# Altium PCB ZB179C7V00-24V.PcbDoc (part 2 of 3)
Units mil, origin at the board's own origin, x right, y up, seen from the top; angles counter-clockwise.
Board outline 6000 x 4000 mil, 2 copper layers (Top Layer, Bottom Layer); 365 components, 297 nets, 1012 pads, 642 vias.
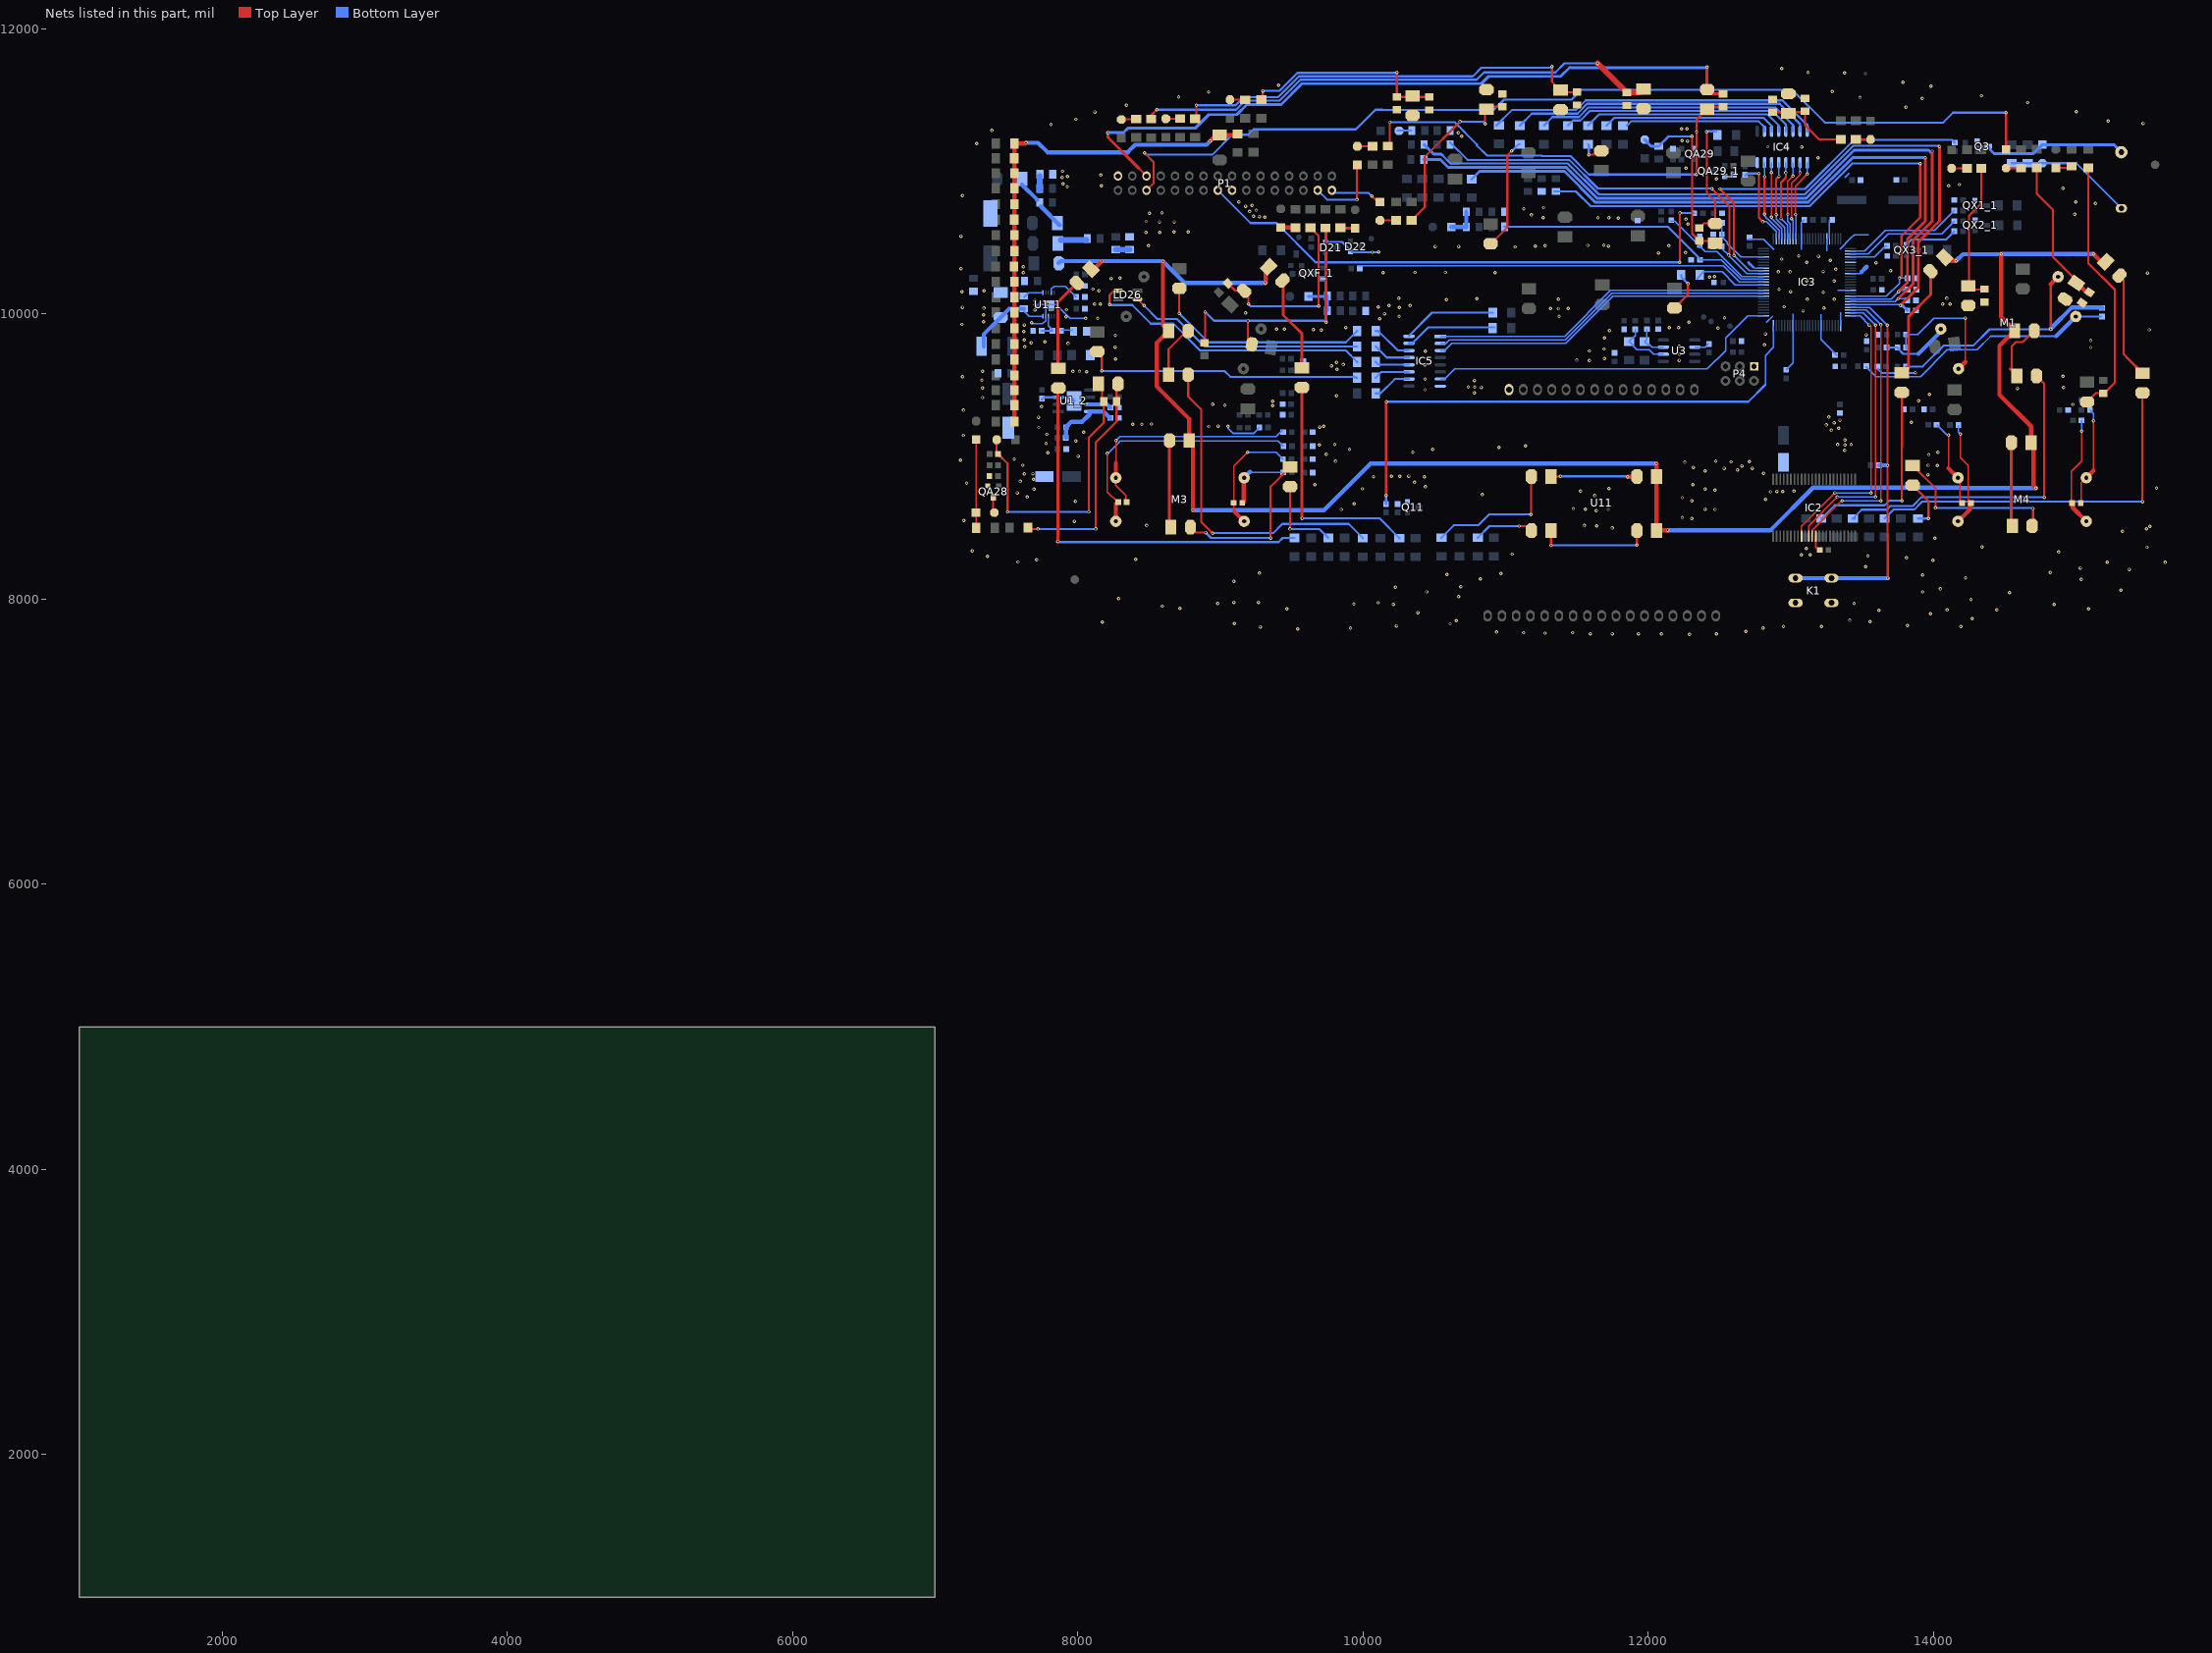
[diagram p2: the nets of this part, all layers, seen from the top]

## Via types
v1: diameter 23.62, hole 11.81, Top Layer to Bottom Layer, 642 vias

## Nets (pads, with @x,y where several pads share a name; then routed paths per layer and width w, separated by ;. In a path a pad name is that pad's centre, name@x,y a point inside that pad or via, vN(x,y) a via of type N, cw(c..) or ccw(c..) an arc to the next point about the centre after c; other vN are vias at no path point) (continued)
GND: C0.2 C1.2 C1_1.2 C2_1.1 C3_1.- C4.- C4_1.2 C5.1 C6.1 C7.1 C7_1.1 C8.1 C8_1.1 C9.1 C10.2 C11.2 C12.1 C13.1 C33.2 C35.2 C37.2 C38.1 C101.1 C102.1 C103.1 C301.1 C401.2 C501.2 CA18.2 CA22.2 CA23.2 CA101.2 CA251.2 CA261.2 CA601.1 CA1101.2 Cm1.1 Cm2.2 Cm3.2 Cm4.1 Cq1.1 Cq2.2 Cq3.2 Cq4.1 Cq21.1 Cq22.2 Cq23.2 Cq24.1 CS1.1 Cz1.1 Cz2.2 Cz3.2 Cz4.1 D3.1 D21.E D22.B DAL16.2 DAL18.2 DAL20.2 DAL21.2 DAL23.2 Ec01.2 Ec02.- IC2.13 IC3.1 IC3.8 IC3.18 IC3.61 IC3.70 IC3.71 IC3.91 IC4.8 IC5.8 K1.1 LC1_1.1 LC2_1.2 LDA03.2 LDA05.2 P1.9 P1.17 P4.2 Q3.E Q11.E QA28.E QA29.E QA29_1.E QX1_1.E QX2_1.E QX3_1.E QXF_1.E R4.1 R6_1.1 R36_1.1 R58.2 R302.2 R402.2 RA053_1.2 RA133.2 RA163.1 RA183.1 RA203.2 RA213.2 RA222.1 RA233.1 RA282.1 RA291_1.1 RA291_4.1 RA603.2 RA1103.1 RA1203.1 RT141.2 RX1_2.2 RX2_2.2 RX3_2.2 U1_1.9 U1_1.11 U1_2.0 U1_2.3 U3.2 U11.31 | length 4302.8
  Top Layer w15: 13175.97,8360.97 IC2.13@13175.97,8440.99
  Bottom Layer w9.8: v1(7678,9938) 7684.81,9931.19 7754,9931.19 7775.69,9952.88 U1_1.9@7775.69,9983.65 7775.69,10038.68 U1_1.11@7801,10064 ; 7701,10040 7725,10064 7793,10064 U1_1.11@7801,10064 ; v1(8056,9968) 7946,9968 7850,10064 U1_1.11@7801,10064 ; U3.2@12327,9767 12327.4,9767.4 12399.4,9767.4 C33.2@12425,9793 ; CS1.1@12697,10524 12810.15,10524 12882.07,10452.07 ; C5.1@12968,9608 13016.57,9656.57 IC3.18@13016.57,9917.85 13016.64,9917.91 13016.64,10000.36 ; 13075.63,10449.37 IC3.61@13075.63,10528.09 13075.63,10639.63 C102.1@13096,10660 ; 13213.42,9997.58 IC3.8@13213.42,9917.85 13213.42,9821.03 C9.1@13326.45,9708 ; 13252.79,10439.21 IC3.70@13252.79,10528.09 ; IC3.71@13272.48,10528.09 C103.1@13272.48,10658.31 ; 13330.09,10163.91 IC3.91@13420.12,10163.91 ; IC3.1@13351.22,9917.85 13351.22,10010.78 ; 13423.66,10532.66 13445,10554 13548,10554
  Bottom Layer w12: v1(9054,9212) 9054,9199 9092,9161 9233,9161 Cz3.2@9275,9203 ; 12832,9944 12833.35,9944 12871,9981 ; 13346,10455 13423.66,10532.66 ; 13382,10958 13408,10984
  Bottom Layer w15: C1_1.2@7749,9401 7763,9415 U1_2.3@7864,9415 ; D21.E@9737.62,10504 9854,10504 9925,10433 v1(10111,10433) ; 13612,9611 13637,9586 13868,9586 v1@13872,9590 ; QX3_1.E@13810.62,10486 13846.62,10522 14090,10522 RX2_2.2@14148,10580
  Bottom Layer w20: U1_2.3@7864,9415 7949,9415 U1_2.0@7974,9390
  other v1: 12291,7753 12095,7755 12479,7755 11595,7757 11748,7757 11932,7757 11277,7761 11126,7764 11471,7764 10937,7768 12685,7772 9543,7790 9913,7796 12805,7797 9280,7805 12949,7808 13216,7808 14192,7808 10236,7812 13817,7815 10612,7826 9099,7827 8172,7838 13556,7842 10655,7849 13414,7851 14273,7863 13981,7897 10386,7905 13618,7920 14097,7923 14446,7925 9468,7931 15088,7932 8717,7934 8593,7950 10213,7962 14847,7963 9937,7966 8983,7969 13445,7969 10108,7974 9096,7977 9267,7977 14264,7997 8288,8004 10671,8018 14535,8045 10447,8050 13925,8050 15316,8061 14050,8071 10229,8083 10687,8086 9094,8124 15038,8137 10823,8142 14226,8148 13926,8168 10589,8172 10969,8179 9274,8181 14821,8186 15373,8208 15031,8218 13526,8228 15626,8257 15220,8258 7582,8260 13997,8272 7713,8275 8407,8278 13812,8288 7368,8299 13541,8302 13074,8309 13137,8310 11047,8315 14879,8329 7262,8338 13109,8355 15497,8363 14340,8364 14011,8426 15327,8475 15494,8492 11748,8498 15519,8510 11640,8512 8484,8515 11552,8515 7976,8545 7201,8551 12306,8564 12240,8570 11637,8619 9848,8628 11720,8628 12470,8628 11560,8630 12399,8631 11476,8632 9938,8667 7985,8685 12306,8689 12824,8699 12240,8711 7647,8715 11627,8725 10838,8732 7576,8745 12859,8752 12944,8754 12902,8755 13024,8756 11527,8758 12468,8764 7693,8772 12399,8772 9997,8773 11726,8775 15565,8778 10438,8787 9664,8803 12314,8803 7221,8813 10363,8818 7597,8825 7691,8839 10430,8857 10075,8858 10200,8860 10259,8860 10322,8862 13963,8872 7627,8878 7686,8879 12811,8881 12400,8898 12626,8906 12533,8917 12730,8917 12317,8924 12659,8934 14029,8937 7616,8938 13964,8938 12257,8959 12583,8962 12709,8963 9809,8966 12474,8968 7179,8975 7555,8981 8003,9003 13968,9011 9744,9015 7791,9026 10350,9029 14033,9030 13379,9043 9906,9050 10491,9050 10955,9064 11140,9074 13380,9080 9695,9081 13330,9083 13424,9084 9803,9085 7779,9092 7986,9109 13380,9116 7198,9148 7784,9155 8042,9171 13286,9183 13337,9197 7727,9203 9697,9206 8921,9210 9726,9211 8986,9213 13249,9221 8387,9226 8450,9226 8517,9227 13304,9235 13845,9239 13345,9254 7724,9275 13267,9276 7200,9324 7746,9348 9368,9357 9032,9360 14979,9365 8946,9367 9368,9388 13896,9391 7332,9413 9816,9426 13973,9435 10781,9445 10436,9468 14588,9478 7332,9480 14914,9483 10829,9485 10739,9487 10784,9487 10782,9533 7328,9536 10436,9543 7193,9560 14910,9562 13875,9588 8063,9594 7967,9596 8013,9596 7332,9598 9819,9611 9779,9635 10435,9642 9862,9644 9816,9660 11589,9673 12219,9674 11500,9675 8266,9683 11693,9686 12220,9717 10437,9738 11587,9740 11691,9754 15104,9764 8263,9767 7630,9768 12218,9772 12816,9782 7933,9792 7675,9796 7770,9804 15104,9813 7626,9817 11694,9832 8264,9849 13528,9853 12822,9860 7623,9876 11730,9883 9707,9887 15514,9888 9652,9889 9395,9893 9450,9893 12491,9901 12148,9904 12213,9904 9880,9905 7626,9922 7188,9926 12286,9941 7340,9944 10117,9965 8140,9969 12536,9972 7919,9980 11376,9982 10254,9983 7340,9993 10151,10001 9177,10007 13087,10022 7700,10027 7921,10029 11372,10036 11316,10038 11440,10038 7342,10040 13232,10042 10256,10045 7193,10046 10107,10049 12955,10050 10331,10057 10184,10059 7700,10062 8119,10068 8159,10068 14065,10068 14118,10068 7793,10071 7734,10074 7701,10094 10587,10100 13116,10102 13306,10102 11372,10103 10800,10107 14095,10109 10251,10111 13228,10152 7188,10154 12999,10156 7344,10162 8150,10162 12918,10172 8107,10174 13112,10230 13304,10230 8234,10249 8297,10251 12431,10259 12465,10262 15502,10287 7620,10289 10142,10290 10927,10290 10366,10291 10578,10291 12912,10295 12997,10295 13228,10297 13700,10302 13315,10312 7183,10316 7620,10330 13597,10359 13112,10361 13277,10376 12938,10384 13194,10404 13056,10407 12074,10428 12262,10429 10067,10432 11067,10470 10508,10473 10671,10473 11209,10475 11722,10476 8496,10477 12146,10477 11279,10478 11576,10480 11689,10482 7182,10545 8478,10571 8576,10571 8776,10574 8676,10575 12280,10630 8574,10645 8677,10645 8481,10649 12265,10663 11790,10671 11264,10674 11648,10674 11724,10674 9313,10678 9273,10683 9232,10685 11181,10694 14991,10698 8502,10705 8591,10710 9205,10718 9252,10725 11128,10737 11269,10745 9179,10755 9224,10760 15138,10775 14999,10784 9131,10785 7193,10829 14908,10882 7927,10892 14108,10897 8166,10899 14183,10907 7898,10913 12480,10947 7892,10956 7928,10963 8162,10973 7895,11000 12266,11022 13191,11094 13077,11171 12839,11172 12961,11174 7291,11194 12277,11213 12239,11215 10692,11247 10670,11271 7399,11286 12235,11297 12272,11297 7813,11328 15472,11337 15226,11353 7987,11365 8120,11416 15003,11418 13809,11449 8343,11462 14662,11482 13923,11511 13486,11517 8708,11522 14338,11530 8918,11556 13291,11558 13984,11597 9408,11605 13788,11624 13524,11685 13378,11690 13121,11693 12938,11722
HEADLIGHT+: DA15.1 P1.15 | length 547.7
  Top Layer w15: v1(9958,10801) 9958,11042 DA15.1@9961,11045
  Bottom Layer w15: P1.15@9682.79,10866.69 9748.48,10801 v1(9958,10801)
HEADLIGHT-: DAL15.2 P1.19 RA153.2 | length 5086
  Top Layer w15: 8430.48,11019 P1.19@8482.79,10966.69
  Top Layer w20: v1(8212,11271) 8212,11237.48 8430.48,11019 ; DAL15.2@12413,11574.82 v1(12413,11731) ; DAL15.2@12413.63,11574.19 12444.82,11543 RA153.2@12525,11543
  Bottom Layer w20: v1(8212,11271) 8323,11271 8356,11304 8827,11304 8920.5,11397.5 9116.5,11397.5 9187.5,11468.5 9426.98,11468.5 9572.99,11614.51 10830.51,11614.51 10882,11666 11387,11666 11451,11730 ; 11458.28,11726 11636,11726 ; 11633.03,11725.69 12407.69,11725.69 v1(12413,11731)
KEY: IC3.97 K1.2 R6.1 | length 2798.1
  Top Layer w9.8: v1@13680,8140 v1(13680,8146)
  Top Layer w15: v1(13678,9920) 13679,9919 v1(13679,8937) 13679,8409 ; v1(13680,8146) 13680,8408
  Bottom Layer w9.8: IC3.97@13420.12,10045.8 13552.2,10045.8 v1(13678,9920) ; v1@13678,8938 v1(13679,8937) ; v1@13679.39,8146.61 v1(13680,8146)
  Bottom Layer w15: v1(13678,9920) v1@13678,9923
  Bottom Layer w30: K1.2@13034.02,8146.61 K1.2@13285.98,8146.61 v1@13679.39,8146.61 ; R6.1@13620,8938 v1@13678,8938
LIGHT: P1.8 RA1102.2 | length 3896.9
  Top Layer w15: v1(12222,10362) 12222,10707 v1(12223,10708)
  Bottom Layer w15: P1.8@8982.79,10866.69 9212.48,10637 9394,10637 9669,10362 v1(12222,10362) ; v1(12223,10708) 12321,10708 RA1102.2@12324,10705
"LOW SHIFT+": DA03.1 P1.3 | length 6930.7
  Top Layer w15: v1(8468,11129) 8532,11065 8532,10915.91 P1.3@8482.79,10866.69 ; DA03.1@14510,11152.5 v1(14510,11412)
  Bottom Layer w15: v1(8468,11129) 8480.81,11116.19 8943.84,11116.19 9079.65,11252 9084.7,11252 9088.7,11256 9195.18,11256 9233.68,11294.5 9950.47,11294.5 10088.47,11432.5 10137.33,11432.5 10139.83,11430 10917.44,11430 10990.44,11503 11464.07,11503 11532.07,11571 13009.82,11571 13239.32,11341.5 14069.15,11341.5 14138.84,11411.19 14509.19,11411.19 v1(14510,11412)
LOWLIGHT+: DA26.1 P1.16 | length 371.1
  Top Layer w15: v1(10062,10826) 10103,10785 DA26.1@10120,10785
  Bottom Layer w15: P1.16@9782.79,10866.69 9800.48,10849 10039,10849 v1(10062,10826)
"MIEXHAUST BRAKE+": CA22.1 IC3.41 RA223.2 | length 2890.5
  Top Layer w15: v1(12447,10877) 12571,10753 12571,10419 v1(12564,10412)
  Bottom Layer w9.8: CA22.1@12518,10491 12518,10458 v1(12564,10412) 12564,10409.93 12691.91,10282.02 IC3.41@12809.88,10282.02
  Bottom Layer w15: RA223.2@10611,11203 10734,11080 11447.35,11080 11648.35,10879 12447,10879 v1(12447,10877)
MIFUEL: C501.1 IC3.94 R505.1 | length 4867.8
  Top Layer w20: v1(13756,10156) 13818,10218 13818,10525 13944,10651 v1(13944,11094)
  Bottom Layer w9.8: IC3.94@13420.12,10104.86 13420.27,10104.7 13704.7,10104.7 v1(13756,10156)
  Bottom Layer w20: R505.1@10764,10945 10818,10999 11413.8,10999 11630.8,10782 13121.2,10782 13135.21,10796.01 13436.2,11097 13941,11097 v1(13944,11094) ; v1(13756,10156) 13770,10170 C501.1@13821,10170
MILIGHT: CA1101.1 IC3.47 RA1104.2 | length 455.7
  Bottom Layer w9.8: CA1101.1@12516,10565 12517,10564 12517,10541.8 12556.47,10502.33 12556.47,10493.47 12650.14,10399.79 12809.54,10399.79 IC3.47@12809.88,10400.13 ; CA1101.1@12518,10563 RA1104.2@12518,10638
MISAFEBELT: CA101.1 IC3.39 RA1204.2 | length 1976.7
  Bottom Layer w9.8: CA101.1@12363,10379 12513.71,10379 12650.05,10242.65 IC3.39@12809.88,10242.65
  Bottom Layer w15: RA1204.2@10990,10610 12140,10610 12363,10387 CA101.1@12363,10379
MISENSE1: CA251.1 IC3.96 RA251.1 | length 5542.6
  Top Layer w20: v1(13769,10059) 13894,10184 13894,10503 14043,10652 v1(14043,11173)
  Bottom Layer w9.8: IC3.96@13420.12,10065.49 13762.51,10065.49 v1(13769,10059)
  Bottom Layer w15: 10558,11112 10614.5,11055.5 11437.2,11055.5 11654.2,10838.5 13097.8,10838.5 13437.3,11178 14038,11178 v1(14043,11173)
  Bottom Layer w20: RA251.1@10430,11187 10497,11120 10550,11120 10558,11112 ; v1(13769,10059) 13783,10059 CA251.1@13818,10024
MISENSE2: CA261.1 IC3.95 RA261.1 | length 5374.2
  Top Layer w20: v1(13752,10105) 13859,10212 13859,10517 13992,10650 v1(13992,11141)
  Bottom Layer w9.8: IC3.95@13420.12,10085.17 13732.17,10085.17 v1(13752,10105) 13810,10105 CA261.1@13820,10095
  Bottom Layer w20: RA261.1@10427,11083 10543,11083 10597.5,11028.5 11426.02,11028.5 11643.02,10811.5 13108.98,10811.5 13444.98,11147.5 13968.12,11147.5 13983.31,11132.31 v1(13992,11141)
MISTATUS: C301.2 IC3.40 R303.1 | length 815
  Bottom Layer w9.8: R303.1@12155,10649 12187,10649 12400,10436 12484,10436 12657.66,10262.34 IC3.40@12809.88,10262.34
MIVOLTAGE: C401.1 IC3.93 R403.1 | length 4072.2
  Top Layer w15: v1(13762,10250) 13777,10265 13777,10546 13908,10677 v1(13908,11054)
  Bottom Layer w9.8: IC3.93@13420.12,10124.54 13671.54,10124.54 13762,10215 v1(13762,10250) 13821,10250 C401.1@13822,10249
  Bottom Layer w15: R403.1@11342,10859 R403.1@11354,10859 11493,10859 11597,10755 13132.38,10755 13431.38,11054 v1(13908,11054)
MOABS: IC3.52 RA291_3.1 | length 624.7
  Top Layer w15: v1(12777,10984) 12777,10674 v1(12805,10646)
  Bottom Layer w9.8: v1(12805,10646) 12831,10646 12898.1,10578.9 12898.1,10528.45 IC3.52@12898.46,10528.08
  Bottom Layer w15: RA291_3.1@12680,10969 12695,10984 v1(12777,10984)
MOAF2301: IC3.38 R3_1.2 | length 2895.4
  Bottom Layer w9.8: R3_1.2@9961.21,10335.79 12527.21,10335.79 12640.03,10222.97 IC3.38@12809.88,10222.97
"MOAIR PRESSURE": IC3.56 IC4.4 | length 565.7
  Top Layer w15: v1(12932,10669) 12932,10921 12966,10955 v1(12966,10990)
  Bottom Layer w9.8: v1(12932,10669) 12977.2,10623.8 IC3.56@12977.2,10528.08 ; v1(12966,10990) IC4.4@12966,11061
MOAIR_FAULT: IC3.33 IC5.3 | length 2424.9
  Bottom Layer w9.8: IC5.3@10543,9743 10573,9743 10624,9794 11421.59,9794 11752.13,10124.54 IC3.33@12809.88,10124.54
MOAIR_HOT: IC3.77 RX1_1.1 | length 846.1
  Bottom Layer w9.8: IC3.77@13420.12,10439.5 13519.5,10439.5 13664,10584 14007,10584 RX1_1.1@14148,10725
MOAIRFLITER: IC3.78 RX2_1.1 | length 824.2
  Bottom Layer w9.8: IC3.78@13420.12,10419.82 13543.82,10419.82 13685,10561 14058,10561 14058.5,10560.5 14147,10649 RX2_1.1@14147,10651
MOBUZZER: IC3.42 RA12.2 | length 2558.1
  Top Layer w15: v1(12504,10876) 12602,10778 v1(12602,10409)
  Bottom Layer w9.8: v1(12602,10409) 12709.29,10301.71 IC3.42@12809.88,10301.71
  Bottom Layer w15: v1(12504,10876) 13100.65,10876 13445.65,11221 14131,11221 RA12.2@14151,11201
MODRIVERALARM: IC3.59 IC4.1 | length 568.6
  Top Layer w9.8: v1(13034,10697) 13034,10896.41 13117,10979.41 v1(13117,10980)
  Bottom Layer w9.8: v1(13034,10697) 13036.26,10694.74 IC3.59@13036.26,10528.09 ; IC4.1@13116,11061 13116,10981 v1(13117,10980)
MOENGINE_FAULT: IC3.57 IC4.3 | length 555.8
  Top Layer w9.8: v1(12980,10698) 12980,10930 v1(13016,10966)
  Bottom Layer w9.8: v1(12980,10698) 12978.79,10696.79 12978.79,10649.51 12996.89,10631.41 IC3.57@12996.89,10528.09 ; v1(13016,10966) IC4.3@13016,11061
MOFUEL: IC3.34 IC5.2 | length 2412.4
  Bottom Layer w9.8: IC5.2@10543,9793 10581,9793 10607,9819 11419.29,9819 11744.52,10144.23 IC3.34@12809.88,10144.23
MOHOT: IC3.58 IC4.2 | length 563
  Top Layer w9.8: v1(13005,10667) 13006.21,10668.21 13006.21,10915.21 13066,10975 v1(13066,10990)
  Bottom Layer w9.8: v1(13005,10667) 13016.57,10655.43 IC3.58@13016.57,10528.09 ; v1(13066,10990) IC4.2@13066,11061
MOLCD: IC3.25 RT131.1 | length 3864.2
  Top Layer w15: v1(10163,8726) 10163,9383 10164,9384 v1(10165,9384)
  Bottom Layer w9.8: 12822,9502 12822,9709 12878.78,9765.78 IC3.25@12878.78,9917.85
  Bottom Layer w15: RT131.1@10163,8666.5 v1(10163,8726) ; v1(10165,9384) 12704,9384 12822,9502
MOLCDCS: IC2.9 IC3.100 | length 1998.9
  Top Layer w9.8: IC2.9@13075.97,8440.99 13075.97,8508.97 13313,8746 v1@13313,8749 ; v1(13551,9922) 13562,9911 13562,8770 13562,8745 v1(13563,8744)
  Bottom Layer w9.8: v1@13313,8749 13318,8744 v1(13563,8744) ; IC3.100@13420.12,9986.75 13486.25,9986.75 v1(13551,9922)
  other v1: 13310,8745
MOLCDDA: IC2.12 IC3.98 | length 2102
  Top Layer w12: IC2.12@13150.97,8440.99 13150.97,8486 13153.06,8486 13355.06,8688 v1(13360,8688) ; v1(13632,8688) 13632,9922 v1(13633,9923)
  Bottom Layer w9.8: IC3.98@13420.12,10026.12 13529.88,10026.12 v1(13633,9923)
  Bottom Layer w12: v1(13360,8688) 13360.31,8687.69 13631.69,8687.69 v1(13632,8688) ; v1(13633,9923) v1@13633,9924
MOLCDWR: IC2.11 IC3.99 | length 2041
  Top Layer w9.8: IC2.11@13125.97,8440.99 13125.97,8513.97 v1(13327,8715) ; v1(13595,8715) v1(13595,9920)
  Bottom Layer w9.8: v1(13327,8715) v1(13595,8715) ; IC3.99@13420.12,10006.43 13508.57,10006.43 v1(13595,9920)
MOOBD: IC3.53 IC4.7 | length 575.4
  Top Layer w15: v1(12816,10698) v1(12816,10962)
  Bottom Layer w9.8: v1(12816,10698) 12816,10688 12838.7,10665.3 12838.99,10665.3 12918.15,10586.15 IC3.53@12918.15,10528.08 ; v1(12816,10962) IC4.7@12816,11061
MOOIL_WATER: IC3.54 IC4.6 | length 563.5
  Top Layer w9.8: v1(12865,10679) v1(12865,10991)
  Bottom Layer w9.8: v1(12865,10679) 12865,10671.64 12937.83,10598.8 IC3.54@12937.83,10528.08 ; v1(12865,10991) 12866,10992 IC4.6@12866,11061
MOOILPRESS: IC3.26 IC5.7 | length 2503.4
  Bottom Layer w9.8: IC5.7@10543,9543 10573,9543 10643,9613 12415,9613 12545,9743 12545,9833 12698.75,9986.75 IC3.26@12809.88,9986.75
MOSAFEBELT: IC3.35 IC5.1 | length 2399.8
  Bottom Layer w9.8: IC5.1@10543,9843 11416,9843 11736.91,10163.91 IC3.35@12809.88,10163.91
MOSPEED1: IC3.81
MOSVS: IC3.43 | length 110.6
  Bottom Layer w9.8: 12742.61,10321.39 IC3.43@12809.88,10321.39
  Bottom Layer w20: 12705.39,10358.61 12736,10328
MOTEMP: IC3.37 RDX1.2 | length 528.6
  Bottom Layer w9.8: RDX1.2@12340,10245 12390,10295 12519,10295 12610.72,10203.28 IC3.37@12809.88,10203.28
MOTMPS: IC3.79 RX3_1.1 | length 287.3
  Bottom Layer w9.8: IC3.79@13420.12,10400.13 13588.13,10400.13 13664,10476 RX3_1.1@13676,10476
MOTRANSFALT: IC3.85 | length 128.4
  Bottom Layer w9.8: IC3.85@13420.12,10282.02 13499.02,10282.02
  Bottom Layer w30: 13497.02,10295.02 13532,10330
MOUREA: IC3.55 IC4.5 | length 566.7
  Top Layer w15: v1(12898,10696) 12898,10945 v1(12918,10965)
  Bottom Layer w9.8: v1(12898,10696) 12898,10665.93 12957.16,10606.78 12957.16,10528.45 IC3.55@12957.52,10528.08 ; IC4.5@12916,11061 12918,11059 v1(12918,10965)
NetB1_1: B1.1 D10.2 RA9.1 RA10.1 | length 900.6
  Bottom Layer w15: RA10.1@14549,11056.5 RA9.1@14662,11056.5 15002.15,11056.5 B1.1@15318.58,10740.07
NetB1_2: B1.2 D10.1 Q3.C | length 1010.8
  Bottom Layer w20: Q3.C@14376.62,11174 14426.62,11124 14702,11124 D10.1@14765,11187 15265.35,11187 B1.2@15318.58,11133.77
NetC2_1: C2.1 U1_1.1 | length 150.3
  Bottom Layer w10: C2.1@7621,10112 7658,10149 U1_1.1@7756,10149
NetC2_1_2: C2_1.2 U1_2.7 | length 154.5
  Bottom Layer w30: U1_2.7@8084,9365 8206,9365 C2_1.2@8229,9342
NetC2_2: C2.2 D3.2 L1_1.2 U1_1.10 | length 589.1
  Bottom Layer w10: C2.2@7621,10022 7659.35,9983.65 U1_1.10@7756,9983.65
  Bottom Layer w30: L1_1.2@7341.75,9773 7341.75,9856.75 D3.2@7460,9975 7521,10036 C2.2@7622,10036
NetC3_2_2: C3_2.2 R57.1 R58.1 U1_2.8 | length 460.9
  Bottom Layer w30: R57.1@7917,9133 7917,9204 C3_2.2@7918,9205 7955,9242 8031,9242 8083,9294 U1_2.8@8083,9315 8181.35,9315 8226.35,9270 R58.1@8230,9270
NetC6_2: C6.2 R3_2.2 U1_1.8 | length 184.5
  Bottom Layer w10: U1_1.8@7795.37,9983.65 7795.37,9915.63 R3_2.2@7824,9887
  Bottom Layer w15: C6.2@7748,9882 R3_2.2@7824,9882
NetC7_1_2: C7_1.2 U1_1.4 | length 241.3
  Bottom Layer w9.8: U1_1.4@7815.06,10149 7815.06,10175.06 7834,10194 7915,10194 C7_1.2@7991,10118
NetC8_1_2: C8_1.2 R3_2.1 | length 81.4
  Bottom Layer w10: R3_2.1@7883,9888 7963,9888 C8_1.2@7964,9889
NetCA18_1: CA18.1 DAL18.1 RA182.2 RA183.2 | length 620.7
  Top Layer w15: RA183.2@12873,11415 13095,11415 CA18.1@13101,11421 13101,11321 13198,11224 RA182.2@13351,11224
NetCA23_1: CA23.1 DAL23.1 RA232.2 RA233.2 | length 1461.8
  Top Layer w15: RA232.2@9288,11502 9298,11512 v1(9298,11564) ; v1(10238,11695) CA23.1@10238,11522 10465,11522 RA233.2@10466,11521
  Bottom Layer w15: v1(9298,11564) 9415,11564 9541.51,11690.51 10233.51,11690.51 v1(10238,11695)
NetD1_1: D1.1 L1.1 | length 177
  Bottom Layer w40: D1.1@7883,10518 L1.1@8060,10518
NetD2_1: D2.1 D3_1.1 L2.1 | length 336.6
  Bottom Layer w30: D3_1.1@7610,10906 L2.1@7716,10800 ; L2.1@7742,10754 D2.1@7874,10622
NetD4_2: D4.2 DL2.1 DL3.1 DL6.1 DL8.1 DL10.1 DL11.1 LD2.1 LD3.1 LD13.1 LD14.1 | length 13299.3
  Top Layer w30: DL2.1@8092.98,10314.46 8114.46,10314.46 v1(8170,10370) ; v1(8598,10368) 8598,9918.76 LD2.1@8637.39,9879.37 8554,9795.98 8554,9492 8781,9265 LD13.1@8781,9112 8808,9085 v1(8808,8623) ; v1(9315,10218) 9318,10221 9318,10308.44 DL3.1@9339.54,10329.98 ; v1(12057,8950) 12059.61,8947.39 DL6.1@12059.61,8859.63 DL8.1@12059.61,8479.63 ; DL8.1@12062.98,8483 v1(12137,8483) v1@12133.63,8479.63 ; DL10.1@14079,10397 14105,10371 v1(14159,10371) ; v1(14475,10419) 14476,10420 14476,9976.76 LD3.1@14570.39,9882.37 14464,9775.98 14464,9432 14685,9211 LD14.1@14685,9097 14702.04,9079.96 14702.04,8794.96 v1(14720,8777) ; v1(15123,10419) 15176,10366 DL11.1@15209,10366
  Bottom Layer w30: D4.2@7867,10356 7881,10370 v1(8170,10370) 8596,10370 v1(8598,10368) 8748,10218 v1(9315,10218) ; v1(8808,8623) 9727,8623 10054,8950 v1(12057,8950) ; v1(12137,8483) 12859,8483 13157.31,8781.31 14189.69,8781.31 14194,8777 v1(14720,8777) ; v1(14159,10371) 14206.69,10418.69 14474.69,10418.69 v1(14475,10419) v1(15123,10419)
NetD7_1: D7.1 R18.1 R19.1 R20.1 R21.1 R22.1 R23.1 R24.1 R25.1 R26.1 R27.1 R28.1 R29.1 R30.1 R31.1 R32.1 R33.1 R34.1 R35.1 R36.1 R37_1.1 | length 3598.8
  Top Layer w30: R18.1@7556,9245 R19.1@7556,9360 R20.1@7556,9464 R21.1@7556,9568 R22.1@7556,9680 R23.1@7556,9789 R24.1@7556,9899 R25.1@7556,10010 R27.1@7556,10225 R29.1@7556,10441 R30.1@7556,10552 R32.1@7556,10770 R33.1@7556,10881 R34.1@7556,10986 R36.1@7556,11195 7633,11195 v1(7638,11200) ; v1(8929,11211) 8972,11254 D7.1@8997,11254 9114,11254 R37_1.1@9122,11262
  Bottom Layer w30: v1(7638,11200) 7722.14,11200 7788.64,11133.5 8351,11133.5 8403,11185.5 8903.5,11185.5 v1(8929,11211)
NetDA03_2: DA03.2 RA131.1 | length 106.2
  Top Layer w15: DA03.2@14519,11020 RA131.1@14624.5,11020 ; 14558,11020.5 14558.5,11021
NetDA05_2: DA05.2 RA051.1 | length 107.2
  Top Layer w15: DA05.2@14129,11020.5 14129.5,11021 RA051.1@14236,11021
NetDA06_1: DA06.1 RA601.2 RA602.1 | length 234.2
  Bottom Layer w20: DA06.1@9618,10122 9748,10122 RA601.2@9751,10125 ; RA602.1@9750,10023 RA601.2@9750,10123
NetDA12_1: DA12.1 RA1201.1 RA1202.2 | length 210.4
  Bottom Layer w30: DA12.1@10620,10609 10724,10609 RA1202.2@10725,10610 RA1201.1@10725,10715
NetDA14_1: DA14.1 RA142.1 | length 111.2
  Top Layer w15: DA14.1@14859,11024 14969.5,11024 RA142.1@14970,11024.5
NetDA15_2: DA15.2 RA152.1 | length 108.4
  Top Layer w15: DA15.2@9961,11175 10068,11175 RA152.1@10069,11176
NetDA18_2: DA18.2 RA181.1 | length 104.4
  Top Layer w15: RA181.1@13457,11224 13458,11223 DA18.2@13561,11223
NetDA20_2: DA20.2 RA201.1 | length 105.2
  Top Layer w15: DA20.2@8306,11364 8407,11364 RA201.1@8410,11367
NetDA21_2: DA21.2 RA211.1 | length 102.8
  Top Layer w15: DA21.2@8618,11369 8718,11369 RA211.1@8719,11370 RA211.1@8720,11371
NetDA22_2: DA22.2 RA221.2 | length 96
  Bottom Layer w15: DA22.2@10243,11286 RA221.2@10339,11286
NetDA23_2: DA23.2 RA231.1 | length 108.4
  Top Layer w15: DA23.2@9067,11502 9174,11502 RA231.1@9175,11501
NetDA26_2: DA26.2 RA161.2 | length 112.2
  Top Layer w15: DA26.2@10120,10655 10231.5,10655 RA161.2@10232,10655.5
NetDA27_1: DA27.1 RA272.2 | length 103.8
  Top Layer w30: DA27.1@9424,10606 9525,10606 RA272.2@9527,10604
NetDA29_2: DA29.2 DAL29.1 RA293.2 RA294.1 | length 1254.3
  Top Layer w15: v1(12308,11246) 12308.81,11245.19 12308.81,10562.19 RA294.1@12359,10512 12456.02,10512 DAL29.1@12471.63,10496.39
  Bottom Layer w15: RA293.2@12075,11176 12143.19,11244.19 12306.19,11244.19 v1(12308,11246)
  Bottom Layer w20: DA29.2@11976,11222 12022,11176 RA293.2@12075,11176
NetDA31_1: DA31.1 DA31_1.1 RA284_1.2 | length 623.2
  Top Layer w12: DA31.1@7286,8605 DA31.1@7289,8602 ; RA284_1.2@7289,8499 DA31.1@7289,8602 ; DA31_1.1@7289,9118 DA31.1@7289,8602
NetDA31_2: DA31.2 QA28.C | length 122.1
  Top Layer w15: QA28.C@7408,8714.38 7408,8613 DA31.2@7416,8605 DA31.2@7422.62,8598.38
NetDA31_2_2: DA31_2.2 LDA31.1 RA283.2 RA285.1 | length 2068.8
  Top Layer w15: DA31_2.2@7430,9117 7431,9116 7431,9028 RA283.2@7442,9017 ; RA283.2@7442,9021.04 RA283.2@7442,9017 ; v1(7509,8611) 7509,8950 RA283.2@7442,9017 ; v1(8079,8611) 8079,9134 8183,9238 RA285.1@8183,9386 8172,9397 8172,9481.76 LDA31.1@8145.39,9508.37
  Bottom Layer w15: v1(7509,8611) v1(8079,8611)
NetDA32_1: DA32.1 RA321.2 | length 103.7
  Top Layer w20: RA321.2@9843,10604 9847,10600 DA32.1@9945,10600
NetDAL14_2: DAL14.2 RA141.2 RA143.1 | length 1833.8
  Top Layer w15: DAL14.2@15078,9382.2 15138.8,9443 RA143.1@15191,9443 15197,9443 15272,9518 15272,10170 15086,10356 RA141.2@15086,11024.5
NetDAL15_1: DAL15.1 RA151.2 RA153.1 | length 3094.6
  Top Layer w15: RA151.2@10174,11177 10189,11192 v1(10189,11344) ; v1@12340,10973 v1(12340,11277) 12340,11362.76 DAL15.1@12413.63,11436.39 12430.24,11453 RA153.1@12525,11453
  Bottom Layer w15: v1(10189,11344) 10644,11344 10800,11188 10800,11180.75 10869.75,11111 11253.26,11111 11258.07,11106.19 11455.81,11106.19 11585,10977 v1(12339,10977) v1@12342,10977
NetDAL16_1: DAL16.1 RA162.1 RA163.2 | length 1239.2
  Top Layer w15: RA162.1@10342,10655.5 10435,10748.5 10435,11102 v1(10681,11348) ; v1(10857,11333) 10857,11424.76 DAL16.1@10866.63,11434.39 10884.24,11452 RA163.2@10978,11452
  Bottom Layer w15: v1(10681,11348) 10842,11348 v1(10857,11333)
NetDAL20_1: DAL20.1 RA202.2 RA203.1 | length 3725.1
  Top Layer w15: RA202.2@8515,11366 8515,11392 v1(8555,11432)
  Top Layer w40: v1(11646,11757) RA203.1@11851,11552 11941.76,11552 DAL20.1@11967.37,11577.61
  Bottom Layer w15: v1(8555,11432) 9110.65,11432 9174.15,11495.5 9415.8,11495.5 9561.8,11641.51 10797.51,11641.51 10849,11693 11350,11693 11414,11757 v1(11646,11757)
NetDAL21_1: DAL21.1 RA212.2 RA213.1 | length 3014.2
  Top Layer w15: RA212.2@8824,11369 8832,11377 v1(8832,11463) ; v1(11326,11734) 11326,11628.98 DAL21.1@11386.37,11568.61 11399.98,11555 RA213.1@11501,11555
  Bottom Layer w15: v1(8832,11463) 9107,11463 9164,11520 9405.65,11520 9551.65,11666.01 10771.01,11666.01 10831,11726 11318,11726 v1(11326,11734)
NetDAL22_2: DAL22.2 RDX8.1 | length 1542.3
  Top Layer w15: v1(8712,10004) 8712,10179.2 DAL22.2@8713,10180.2
  Bottom Layer w15: v1(8712,10004) 8916,9800 9880,9800 RDX8.1@9960,9880
NetDAL27_2: DAL27.2 RA271.1 RA273.2 | length 1318.7
  Top Layer w15: RA273.2@9053.64,10213.64 9104.3,10162.98 DAL27.2@9166.45,10162.98 9198,10131.43 v1(9198,10069) ; RA271.1@9632,10604 9690,10546 9690,10056 v1@9693,10053
  Bottom Layer w15: v1(9198,10069) 9214,10053 v1@9693,10053
  other v1: 9691,10055
NetDAL29_2: DAL29.2 RA292.1 RA294.2 | length 864.4
  Top Layer w15: RA294.2@12359,10602 12391.19,10634.19 DAL29.2@12471.63,10634.19 12471.63,10787.37 12411,10848 12411,11275 v1(12409,11277)
  Bottom Layer w15: v1(12409,11277) 12413,11281 RA292.1@12477,11281
NetDAL32_2: DAL32.2 RA322.2 RA323.1 | length 1936.7
  Top Layer w15: RA323.1@8888,9797 8894,9803 v1(8894,10013) ; v1(9194,9950) 9194,9813.23 DAL32.2@9221.3,9785.93 ; v1@9741,9942 v1(9742,9941)
  Top Layer w20: RA322.2@9738,10603 9741,10600 v1@9741,9942
  Bottom Layer w15: v1(8894,10013) 8955.69,9951.31 v1@9194,9951.31 ; v1(9194,9950) v1@9194,9951.31 ; v1(9742,9941) 9731.69,9951.31 v1@9194,9951.31
NetDL1_1: DL1.1 DL2.2 | length 640
  Top Layer w20: DL1.1@7861.37,9632.61 7861.37,10082.85 DL2.2@7995.55,10217.02
NetDL1_2: DL1.2 RL3.2 | length 2756.5
  Top Layer w20: v1(7861,8404) 7861.37,8404.37 DL1.2@7861.37,9494.81
  Bottom Layer w15: v1@7867.5,8399.5 7867.81,8399.19 9408.69,8399.19 9437.5,8428 RL3.2@9521,8428
NetDL3_2: DL3.2 DL4.1 | length 666.4
  Top Layer w20: DL3.2@9436.98,10232.55 9442.31,10227.21 9442.31,9991.06 9573.37,9860 DL4.1@9573.37,9622.61
NetDL4_2: DL4.2 RL8.2 | length 1658.1
  Top Layer w15: v1@9573.37,8567.63 v1(9575,8566)
  Top Layer w20: v1@9573.37,8567.63 DL4.2@9573.37,9484.81
  Bottom Layer w15: v1(9575,8566) 10117,8566 RL8.2@10256,8427
NetDL5_1: DL5.1 DL6.2 | length 603.9
  Top Layer w15: DL5.1@11319.61,8859.63 11385.63,8859.63 v1(11386,8860) ; DL6.2@11920.18,8858 DL6.2@11921.81,8859.63
  Top Layer w30: v1(11856,8858) DL6.2@11920.18,8858
  Bottom Layer w15: v1(11386,8860) 11854,8860 v1(11856,8858)
NetDL5_2: DL5.2 RL10.1 | length 963.3
  Top Layer w15: v1(11179,8593) 11179,8856.82 DL5.2@11181.81,8859.63
  Bottom Layer w15: RL10.1@10551,8430 10638,8517 10808,8517 10884,8593 v1(11179,8593)
NetDL7_1: DL7.1 DL8.2 | length 806.6
  Top Layer w15: v1@11319,8372 11319.61,8372.61 DL7.1@11319.61,8479.63 ; DL8.2@11921.81,8479.63 11921.81,8378.19 v1(11922,8378)
  Bottom Layer w15: v1@11325,8378 v1(11922,8378)
  other v1: 11320,8377
NetDL7_2: DL7.2 RL12.1 | length 422.4
  Top Layer w15: v1(11096,8511) 11150.44,8511 DL7.2@11181.81,8479.63
  Bottom Layer w15: RL12.1@10806,8430 10887,8511 v1(11096,8511)
NetDL9_1: DL9.1 DL10.2 | length 797.5
  Top Layer w20: DL9.1@13779,9586 13825,9632 13825,9980 13981.56,10136.56 DL10.2@13981.56,10299.56
NetDL9_2: DL9.2 RL9_1.2 | length 1425.1
  Top Layer w15: DL9.2@13779,9448.2 13780,9447.2 13780,9111 ; v1(13780,8688) 13779,8689 13779,9110 13780,9111 ; 13780,9065 13780,9111
  Bottom Layer w15: RL9_1.2@13215,8565 13308,8658 13659,8658 13691,8690 13778,8690 v1(13780,8688)
NetDL11_2: DL11.2 DL12.1 | length 751.1
  Top Layer w15: DL11.2@15306.44,10268.56 15334,10241 15334,9717 15366,9685
  Top Layer w20: 15366,9685 DL12.1@15467,9584
NetDL12_2: DL12.2 RL12_1.1 | length 2713.3
  Top Layer w15: 15465,8780 15465,8869 ; DL12.2@15467,9446.2 15465,9444.2 15465,8869 ; v1(15468,8683) 15466,8685 15466,8868 15465,8869
  Bottom Layer w15: RL12_1.1@13658,8565 13720.5,8627.5 13866.15,8627.5 13921.82,8683.18 15461.82,8683.18 15462,8683 v1(15468,8683)
NetDL15_1: DL15.1 LD13.2 | length 612.1
  Top Layer w20: LD13.2@8643.2,9112 8643.2,8513.8 DL15.1@8653,8504
NetDL15_2: DL15.2 DL17.1 | length 1148.4
  Top Layer w15: DL15.2@8790.8,8504 8828.8,8466 v1(8898,8466) ; v1(9353,8428) 9353,8789 DL17.1@9490,8926
  Bottom Layer w15: v1(8898,8466) 8936,8428 v1(9353,8428)
NetDL16_1: DL16.1 LD14.2 | length 587.2
  Top Layer w20: LD14.2@14547.2,9097 14547.2,8520.8 DL16.1@14555,8513
NetDL16_2: DL16.2 DL18.1 | length 1176.3
  Top Layer w15: DL18.1@13855,8936 14017,8774 14017,8639 v1(14015,8639) ; DL16.2@14692.8,8513 14699,8519.2 14699,8635 v1(14698,8635)
  Bottom Layer w15: v1(14015,8639) 14694,8639 v1(14698,8635)
NetDL17_2: DL17.2 RL17.2 | length 592.7
  Top Layer w15: v1(9489,8491) 9489,8787.2 DL17.2@9490,8788.2
  Bottom Layer w15: v1(9489,8491) 9695,8491 RL17.2@9758,8428
NetDL18_2: DL18.2 RL18.2 | length 353.2
  Top Layer w15: DL18.2@13855,8798.2 13966,8687.2 v1(13966,8565)
  Bottom Layer w15: RL18.2@13892,8565 v1(13966,8565)
NetFBm1_2: FBm1.2 M1.1 Rm1.2 | length 2016.7
  Top Layer w15: v1(14823,9892) 14823,10208.09 M1.1@14874.95,10260.05
  Top Layer w30: 14823,10208.09 M1.1@14874.95,10260.05
  Bottom Layer w15: FBm1.2@13807,9631 FBm1.2@13809,9631 13925,9631 14071,9777 14280,9777 14395,9892 v1(14823,9892) ; Rm1.2@15175,10046 Rm1.2@15175.19,10045.81
  Bottom Layer w30: v1(14823,9892) 14823,9896.47 14972.34,10045.81 15175.19,10045.81 15179.19,10045.81 Rm1.2@15184,10041
NetFBm2_2: FBm2.2 M1.2 Rm1.1 | length 1852
  Bottom Layer w12: FBm2.2@13530,9628 13598,9560 13910,9560 14098,9748 14307,9748 14402,9843 14860.75,9843 ; M1.2@14999.06,9981.31 15178.31,9981.31 Rm1.1@15179,9982
  Bottom Layer w30: 14860.75,9843 M1.2@14999.06,9981.31
NetFBm3_1: FBm3.1 M1.3 Rm2.1 | length 941.7
  Top Layer w9.8: 14224,9662.18 v1(14224,9970)
  Top Layer w30: M1.3@14177.22,9615.4 14224,9662.18
  Bottom Layer w9.8: FBm3.1@13802,9857 13809,9850 Rm2.1@13809,9753 ; FBm3.1@13810,9857 13892,9857 14005,9970 v1(14224,9970)
NetFBm4_1: FBm4.1 M1.4 Rm2.2 | length 484.8
  Bottom Layer w15: FBm4.1@13672,9765 Rm2.2@13749,9765 13749,9760 13789,9720 13896,9720 ; M1.4@14053.12,9877.12 M1.4@14053.12,9894.14
  Bottom Layer w30: 13896,9720 M1.4@14053.12,9877.12
NetFBq1_2: FBq1.2 M3.1 Rq1.2 | length 1800.5
  Top Layer w9.8: v1(8208,9021) 8208,8752 8279,8681 Rq1.2@8267.54,8669.54
  Top Layer w30: M3.1@8267.54,8545.12 Rq1.2@8267.54,8669.54
  Bottom Layer w9.8: v1(8208,9021) 8215.07,9021 8294.21,9100.14 8294.21,9107.21 8295.43,9108.43 9406.57,9108.43 FBq1.2@9443,9072
NetFBq2_2: FBq2.2 M3.2 Rq1.1 | length 1661.4
  Top Layer w9.8: M3.2@8267.54,8850.23 8267.54,8798.46 8339,8727 Rq1.1@8339,8681 ; 8268,8953 v1(8268,9111)
  Top Layer w30: M3.2@8267.54,8850.23 8267.54,8952.54 8268,8953
  Bottom Layer w9.8: v1(8268,9111) 8297,9140 9392,9140 9436,9184 FBq2.2@9439.4,9184
NetFBq3_1: FBq3.1 M3.3 Rq2.1 | length 472.8
  Top Layer w9.8: M3.3@9164,8847.08 M3.3@9167.15,8850.24
  Top Layer w30: Rq2.1@9164,8677 M3.3@9164,8847.08
  Bottom Layer w9.8: 9209.46,8892.54 9214,8888 FBq3.1@9446,8888
  Bottom Layer w30: M3.3@9167.15,8850.24 9209.46,8892.54
NetFBq4_1: FBq4.1 M3.4 Rq2.2 | length 820.2
  Top Layer w9.8: 9097,8615.27 9097,8934 v1(9192,9029)
  Top Layer w30: 9097,8615.27 M3.4@9167.15,8545.12
  Bottom Layer w9.8: v1(9192,9029) 9193,9028 9393,9028 FBq4.1@9440,8981
NetFBq5_2: FBq5.2 M4.1 Rq21.2 | length 795.8
  Top Layer w9.8: v1(14189,9157) 14189,8993 14246,8936 14246,8618.06
  Top Layer w30: M4.1@14173.06,8545.12 14246,8618.06 14255,8627.06 Rq21.2@14255,8675
  Bottom Layer w9.8: FBq5.2@14177,9220 FBq5.2@14176,9220 14176,9170 v1(14189,9157)
NetFBq6_2: FBq6.2 M4.2 Rq21.1 | length 628.8
  Top Layer w9.8: 14106,8917.29 v1(14106,9150) ; M4.2@14173.06,8850.23 14188,8835.29 Rq21.1@14188,8667
  Top Layer w30: 14106,8917.29 M4.2@14173.06,8850.23
  Bottom Layer w9.8: FBq6.2@14024,9222 14096,9150 v1(14106,9150)
NetFBq7_1: FBq7.1 M4.3 Rq22.1 | length 696
  Top Layer w9.8: Rq22.1@15038,8676 15038,8815.57 M4.3@15072.67,8850.24 ; 15124,8901.57 v1(15124,9250)
  Top Layer w30: M4.3@15072.67,8850.24 15124,8901.57
  Bottom Layer w9.8: FBq7.1@15099,9326 FBq7.1@15099,9325 15124,9300 v1(15124,9250)
NetFBq8_1: FBq8.1 M4.4 Rq22.2 | length 802.8
  Top Layer w9.8: 14967,8650.78 14967,8895 15041,8969 v1(15041,9178)
  Top Layer w30: Rq22.2@14978,8675 14978,8639.78 M4.4@15072.67,8545.12
  Bottom Layer w9.8: FBq8.1@15039,9253 15039,9180 v1(15041,9178)
NetIC4_10: IC4.10 RDX3.2 | length 1023
  Bottom Layer w15: RDX3.2@11851,11320 11881,11350 12776,11350 12816,11310 IC4.10@12816,11281
NetIC4_11: IC4.11 RDX5.1 | length 1241.4
  Bottom Layer w15: RDX5.1@11708,11320 11763,11375 12809,11375 12866,11318 IC4.11@12866,11281
NetIC4_12: IC4.12 RD14_1.1 | length 1443.4
  Bottom Layer w15: RD14_1.1@11578,11320 11657.5,11399.5 12837.5,11399.5 12916,11321 IC4.12@12916,11281
NetIC4_13: IC4.13 RDX12.1 | length 1658.8
  Bottom Layer w15: RDX12.1@11437,11320 11473,11356 11524.96,11356 11592.96,11424 12870,11424 12966,11328 IC4.13@12966,11281
NetIC4_14: IC4.14 RDX9.2 | length 1896
  Bottom Layer w15: RDX9.2@11269,11320 11329.5,11380.5 11514.81,11380.5 11582.81,11448.5 12892.5,11448.5 13015,11326 13016,11326 IC4.14@13016,11281
NetIC4_15: IC4.15 RDX2.2 | length 2138
  Bottom Layer w15: RDX2.2@11100,11320 11185,11405 11504.66,11405 11572.66,11473 12923.65,11473 13066,11330.65 IC4.15@13066,11281
NetIC4_16: IC4.16 RDX4.1 | length 2374.4
  Bottom Layer w15: RDX4.1@10935,11320 11044.5,11429.5 11494.51,11429.5 11562.51,11497.5 12942.5,11497.5 13116,11324 13116,11329
  Bottom Layer w20: IC4.16@13116,11281 13116,11324
NetIC5_10: IC5.10 RDX6.1 | length 274.8
  Bottom Layer w15: RDX6.1@10090,9442 10123,9442 10224,9543 IC5.10@10323,9543
NetIC5_11: IC5.11 RD13_1.1 | length 249.6
  Bottom Layer w15: RD13_1.1@10090,9553 10130,9593 IC5.11@10323,9593
NetIC5_12: IC5.12 RD26_2.1 | length 241.3
  Bottom Layer w15: RD26_2.1@10090,9663 10110,9643 IC5.12@10323,9643
NetIC5_13: IC5.13 RD26_1.2 | length 265.3
  Bottom Layer w15: RD26_1.2@10090,9771 10168,9693 IC5.13@10323,9693
NetIC5_14: IC5.14 RDX8.2 | length 289.7
  Bottom Layer w15: RDX8.2@10090,9880 10108,9880 10245,9743 IC5.14@10323,9743
NetIC5_15: IC5.15 RDX14.1 | length 657.9
  Bottom Layer w15: IC5.15@10329,9799 IC5.15@10323,9793 10347,9793 10459,9905 RDX14.1@10926,9905
NetIC5_16: IC5.16 RDX13.1 | length 658.1
  Bottom Layer w15: IC5.16@10323,9843 10323,9846 10485,10008 RDX13.1@10911,10008
NetLC1_1: LC1.1 LC1_1.2 | length 97
  Bottom Layer w40: LC1.1@8267,10451 LC1_1.2@8364,10451
NetLC2_2: LC2.2 LC2_1.1 | length 100.8
  Bottom Layer w40: LC2.2@7733,10865 7735,10867 LC2_1.1@7735,10965
NetLCan1_1: LCan1.1 R73.1 U3.6 | length 382.1
  Bottom Layer w9.8: LCan1.1@11910,9892 11910,9850 R73.1@11866,9806 11922,9750 12006,9750 12039,9717 U3.6@12107,9717
NetLCan2_1: LCan2.1 R78.2 U3.7 | length 242.8
  Bottom Layer w9.8: LCan2.1@11992,9893 11992,9822 R78.2@11975,9805 11995,9785 12009,9785 12027,9767 U3.7@12107,9767
NetLD1_1: LD1.1 LD2.2 | length 390
  Top Layer w15: LD1.1@8637.39,9573.37 8637.39,9752.39 8764.37,9879.37 LD2.2@8775.19,9879.37
  Top Layer w20: LD1.1@8622.81,9587.95 LD1.1@8637.39,9573.37
NetLD1_2: LD1.2 RL1.2 | length 2304.5
  Top Layer w15: LD1.2@8775.19,9573.37 8775.19,9419.81 8867,9328 8867,8541 v1(8946,8462)
  Bottom Layer w15: v1(8946,8462) 9370,8462 9435,8527 9900,8527 RL1.2@10000,8427
NetLD3_2: LD3.2 LD4.1 | length 446.8
  Top Layer w15: 14535,9614.76 LD4.1@14549.38,9600.38 ; LD4.1@14584.39,9565.37 LD4.1@14549.38,9600.38 ; LD3.2@14708.19,9882.37 14627.82,9802 14578,9802 14549.38,9773.38 LD4.1@14549.38,9600.38
NetLD4_2: LD4.2 RL5.2 | length 2294.4
  Top Layer w15: LD4.2@14722.19,9565.37 14777,9510.56 14777,8716 v1(14779,8714)
  Bottom Layer w15: RL5.2@13450,8565 RL5.2@13436,8565 13497.5,8626.5 13672.5,8626.5 13698,8652 13856,8652 13919,8715 14778,8715 v1(14779,8714)
NetLD13_1_2: LD13_1.2 RD13_1.2 | length 1945.2
  Top Layer w15: LD13_1.2@8136.37,9723.81 8170,9690.18 8170,9678 8169,9677 v1(8169,9600)
  Bottom Layer w15: v1(8169,9600) 8170,9599 9030,9599 9070.43,9558.57 RD13_1.2@9934.57,9558.57 ; RD13_1.2@9937,9561 9945,9553 RD13_1.2@9958,9553
NetLD14_1_2: LD14_1.2 RD14_1.2 | length 175.6
  Top Layer w15: v1(11584,11116) 11645.2,11116 LD14_1.2@11672,11142.8
  Bottom Layer w15: RD14_1.2@11578,11190 11584,11184 v1(11584,11116)
NetLD26_1: LD26.1 RD26_1.1 | length 1678.9
  Top Layer w12: LD26.1@8419,10104 v1(8465,10058)
  Bottom Layer w15: v1(8465,10058) 8559,9964 8696,9964 8889,9771 RD26_1.1@9960,9771
NetLD26_4: LD26.4 RD26_2.2 | length 2040.7
  Top Layer w15: v1(8225,10065) 8225,10132 8254.09,10161.09 LD26.4@8285.14,10161.09
  Bottom Layer w15: v1(8225,10065) 8228,10062 8383,10062 8514,9931 8671,9931 8859,9743 9880,9743 RD26_2.2@9960,9663
NetLDA03_1: LDA03.1 RA132.2 RA133.1 | length 1043
  Top Layer w15: RA132.2@14725,11023 14725,10844 14839,10730 14839,10399 15004,10234 LDA03.1@15004,10212
  Top Layer w30: LDA03.1@15004,10212 15013,10212 RA133.1@15089,10136
NetLDA05_1: LDA05.1 RA052.2 RA053_1.1 | length 990
  Top Layer w15: RA052.2@14337,11021 14337,10776 14250,10689 14250,10195 14274,10171 RA053_1.1@14368,10171
NetLDA31_2: LDA31.2 RA284.2 RA285.2 | length 1560.8
  Top Layer w15: RA284.2@7652,8500 7661,8491 v1(7722,8491) ; v1(8127,8491) 8127,9099 8273,9245 RA285.2@8273,9386 8273,9498.18 LDA31.2@8283.19,9508.37
  Bottom Layer w15: v1(7722,8491) v1(8127,8491)
NetLDX1_2: LDX1.2 RDX1.1 | length 292.7
  Top Layer w15: LDX1.2@12184.37,10039.81 12280,10135.44 v1(12280,10212)
  Bottom Layer w15: RDX1.1@12232,10273 12232,10260 v1(12280,10212)
NetLDX2_2: LDX2.2 RDX2.1 | length 785.1
  Top Layer w15: LDX2.2@10902,10495.2 11013,10606.2 11013,11112 v1(11044,11143)
  Bottom Layer w15: v1(11044,11143) 11046,11143 RDX2.1@11093,11190 ; RDX2.1@11090,11190 RDX2.1@11093,11190 ; RDX2.1@11100,11190 RDX2.1@11093,11190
